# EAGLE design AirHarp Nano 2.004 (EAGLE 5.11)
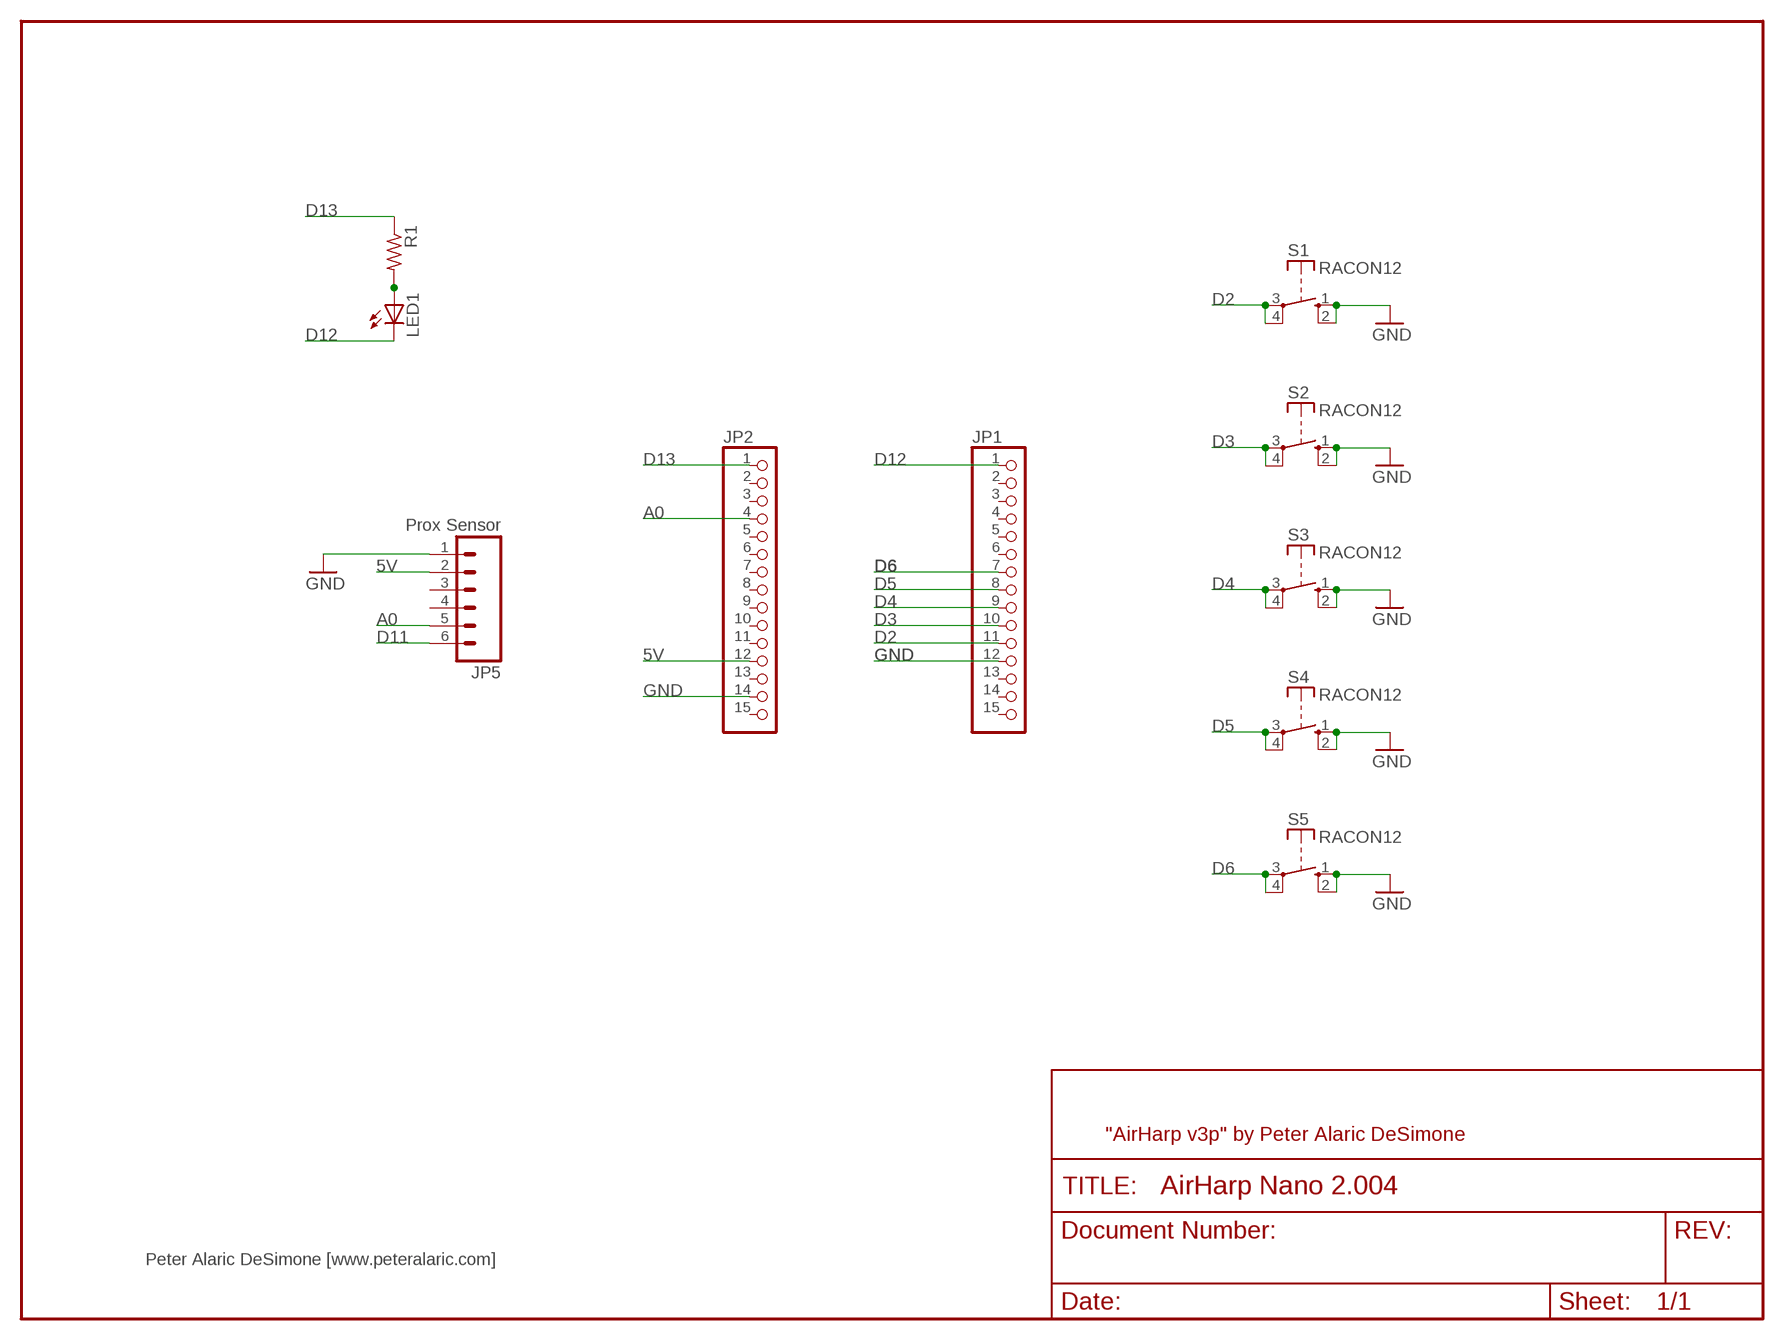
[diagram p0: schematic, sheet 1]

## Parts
JP1  PINHD-1X15  [1X15]
JP2  PINHD-1X15  [1X15]
JP5  Prox Sensor  M06SIP  [1X06]
LED1  LED10MM  [LED10MM]
R1  R-US_0207/7  [0207/7]
S1  RACON12  [RACON12]
S2  RACON12  [RACON12]
S3  RACON12  [RACON12]
S4  RACON12  [RACON12]
S5  RACON12  [RACON12]

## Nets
5V: JP2.12 JP5.2
A0: JP2.4 JP5.5
D2: JP1.11 S1.3(P) S1.4(P)
D3: JP1.10 S2.3(P) S2.4(P)
D4: JP1.9 S3.3(P) S3.4(P)
D5: JP1.8 S4.3(P) S4.4(P)
D6: JP1.7 S5.3(P) S5.4(P)
D11: JP5.6
D12: JP1.1 LED1.K(C)
D13: JP2.1 R1.1
GND: JP1.12 JP2.14 JP5.1 S1.1(S) S1.2(S) S2.1(S) S2.2(S) S3.1(S) S3.2(S) S4.1(S) S4.2(S) S5.1(S) S5.2(S)
N$1: LED1.A R1.2
Unconnected: JP1.2 JP1.3 JP1.4 JP1.5 JP1.6 JP1.13 JP1.14 JP1.15 JP2.2 JP2.3 JP2.5 JP2.6 JP2.7 JP2.8 JP2.9 JP2.10 JP2.11 JP2.13 JP2.15 JP5.3 JP5.4

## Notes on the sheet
- "AirHarp v3p" by Peter Alaric DeSimone
- Peter Alaric DeSimone [www.peteralaric.com]

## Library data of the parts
JP1 JP2 = pinhead:PINHD-1X15: PIN HEADER
JP5 = SparkFun:M06: Header 6 Standard 6-pin 0.1" header. Use with straight break away headers (SKU : PRT-00116), right angle break away headers (PRT-00553), swiss pins (PRT-00743), machine pins (PRT-00117), and female headers (PRT-00115). Molex polarized connector foot print use with SKU : PRT-08094 with associated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
LED1 = led:LED: LED
R1 = resistor:R-US_: RESISTOR, American symbol
S1-S5 = switch-misc:RACON12: ITT SWITCH

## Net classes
1 power: width 0.254 mm

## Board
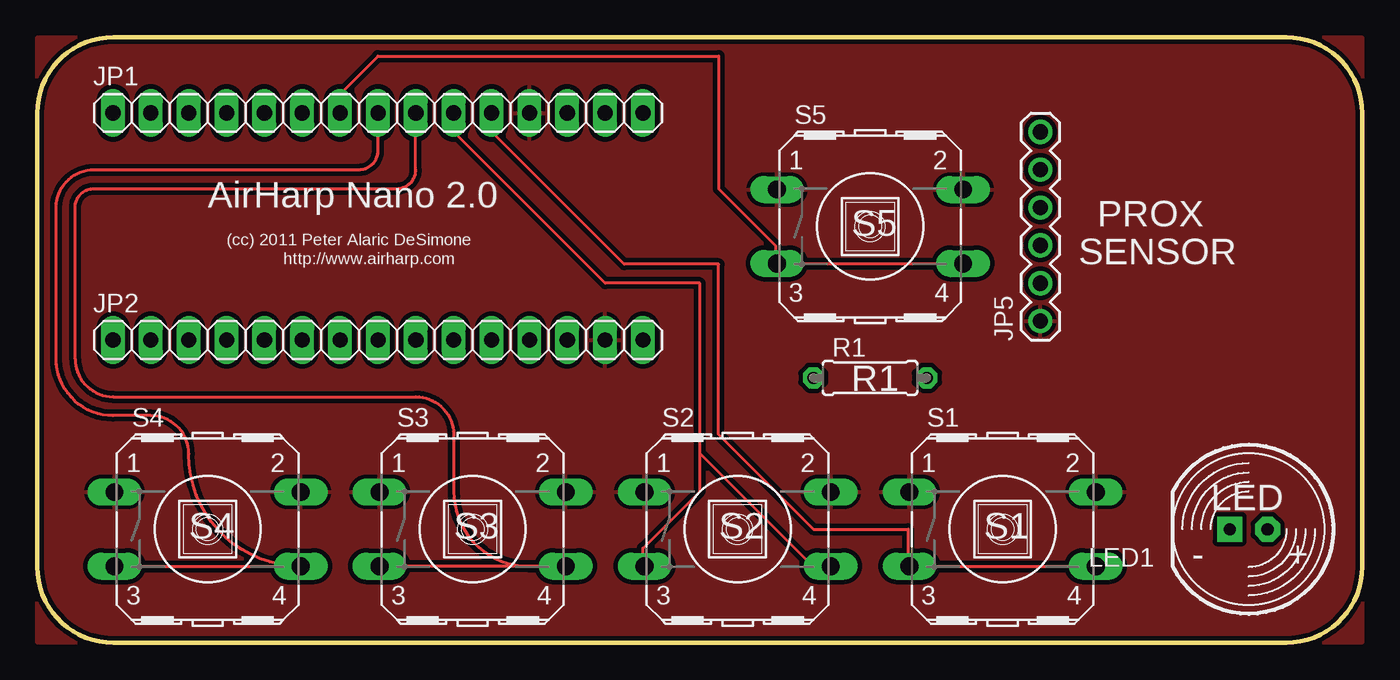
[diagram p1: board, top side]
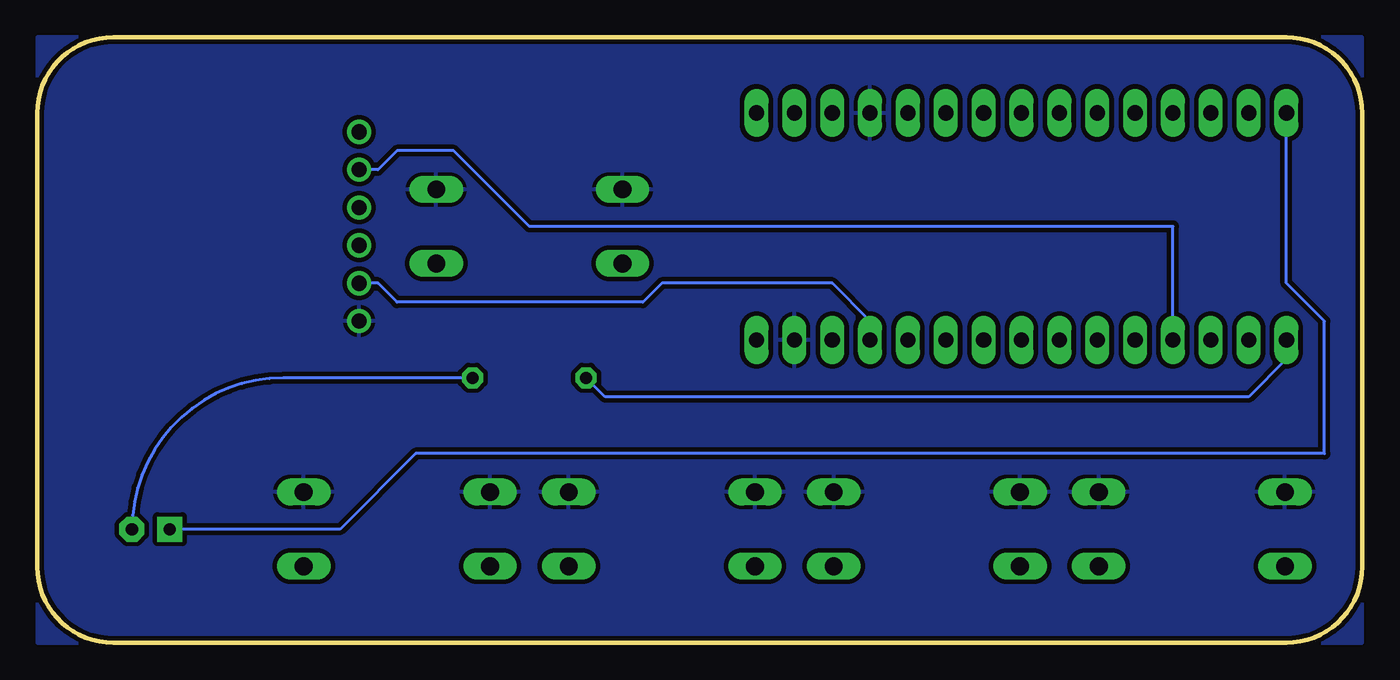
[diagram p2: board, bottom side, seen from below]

Size 88.9 x 40.64 mm. Coordinates in mm from the lower left corner, seen from the top.
Outline: 0,35.56 arc-90 5.08,40.64 83.82,40.64 arc-90 88.9,35.56 88.9,5.08 arc-90 83.82,0 5.08,0 arc-90 0,5.08 0,35.56
Copper layers (1*16): Top 0.035mm / dielectric 1.5mm / Bottom 0.035mm
Design rules "SparkFun": minimum track width 8mil, minimum drill 20mil, track to track 8mil, track to pad 8mil, pad to pad 8mil, via to via 8mil, smd to smd 8mil, copper to edge 10mil, drill to drill 8mil, minimum pad ring 12mil, minimum via ring 10mil, stop-mask expansion 4mil, vias tented up to drill 20mil, thermal gap 10mil

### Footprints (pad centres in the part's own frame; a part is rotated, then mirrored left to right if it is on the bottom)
1X15 = drill 1.016 long: 1 -17.78,0; 2 -15.24,0; 3 -12.7,0; 4 -10.16,0; 5 -7.62,0; 6 -5.08,0; 7 -2.54,0; 8 0,0; 9 2.54,0; 10 5.08,0; 11 7.62,0; 12 10.16,0; 13 12.7,0; 14 15.24,0; 15 17.78,0
1X06 = drill 1.016 round: 1 0,0; 2 2.54,0; 3 5.08,0; 4 7.62,0; 5 10.16,0; 6 12.7,0
LED10MM = drill 0.813 pad 1.676 octagon: A -1.27,0 | drill 0.813 pad 1.676 square: K 1.27,0
0207/7 = drill 0.813 octagon: 1 -3.81,0; 2 3.81,0
RACON12 = drill 1.194 long: 1 -6.248,2.489; 2 6.248,2.489; 3 -6.248,-2.489; 4 6.248,-2.489

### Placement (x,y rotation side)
JP1  22.86,35.56 0 top
JP2  22.86,20.32 0 top
JP5  67.31,21.59 90 top
LED1  81.28,7.62 180 top
R1  55.88,17.78 0 top
S1  64.77,7.62 0 top
S2  46.99,7.62 0 top
S3  29.21,7.62 0 top
S4  11.43,7.62 0 top
S5  55.88,27.94 0 top

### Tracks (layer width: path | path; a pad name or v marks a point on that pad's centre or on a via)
5V
  Bottom 0.203: JP2.12 33.02,21.59 35.56,24.13 46.99,24.13 48.26,22.86 64.77,22.86 66.04,24.13 JP5.2
A0
  Bottom 0.203: JP2.4 12.7,27.94 55.88,27.94 60.96,33.02 64.77,33.02 66.04,31.75 JP5.5
D2
  Top 0.203: JP1.11 30.48,34.29 39.37,25.4 45.72,25.4 45.72,13.97 52.07,7.62 58.42,7.62 58.42,5.08 S1.3 S1.4
D3
  Top 0.203: JP1.10 27.94,34.29 38.1,24.13 44.45,24.13 44.45,12.7 | 44.45,12.7 44.45,10.16 40.64,6.35 40.64,5.08 S2.3 | 44.45,12.7 52.07,5.08 S2.4
D4
  Top 0.203: 24.18,5.13 S3.3 S3.4 32.97,5.13 arc-90 27.94,10.16 27.94,13.97 arc90 25.4,16.51 5.08,16.51 arc-90 2.54,19.05 2.54,29.21 arc-90 3.81,30.48 24.13,30.48 arc90 25.4,31.75 JP1.9
D5
  Top 0.203: S4.3 S4.4 arc-90 10.16,12.65 10.16,12.7 arc90 7.62,15.24 5.08,15.24 arc-90 1.27,19.05 1.27,29.21 arc-90 3.81,31.75 21.59,31.75 arc90 22.86,33.02 JP1.8
D6
  Top 0.203: JP1.7 20.32,36.83 22.86,39.37 45.72,39.37 45.72,30.48 49.53,26.67 49.53,25.4 S5.3 S5.4
D12
  Bottom 0.203: JP1.1 5.08,24.13 2.54,21.59 2.54,12.7 63.5,12.7 68.58,7.62 LED1.K
D13
  Bottom 0.203: R1.1 50.8,16.51 7.62,16.51 5.08,19.05 JP2.1
GND
  pour Top (isolate 0.305): 0,40.64 88.9,40.64 88.9,0 0,0
  pour Bottom (isolate 0.305): 0,40.64 88.9,40.64 88.9,0 0,0
N$1
  Bottom 0.203: LED1.A arc90 72.39,17.78 R1.2

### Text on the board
_tsilk: AirHarp Nano 2.0 | PROX | (cc) 2011 Peter Alaric DeSimone | S5 | http://www.airharp.com | SENSOR | R1 | LED | S4 | S3 | S2 | S1 | - | +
